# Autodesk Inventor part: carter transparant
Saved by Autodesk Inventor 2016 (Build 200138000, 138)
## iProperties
Created: 2013-10
Part Number: carter transparant
Material: Générique
Document SubType Name: Modeling
Designer: Bruno
Density: 1 g/cm^3
Appearance: Par défaut
Author: Bruno
Sending System: SolidWorks 2013
Last Author: christophe
Last Saved: 2014-02-15
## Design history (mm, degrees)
feature "Enlèv. mat.-Extru.33"
node "Solide1"
